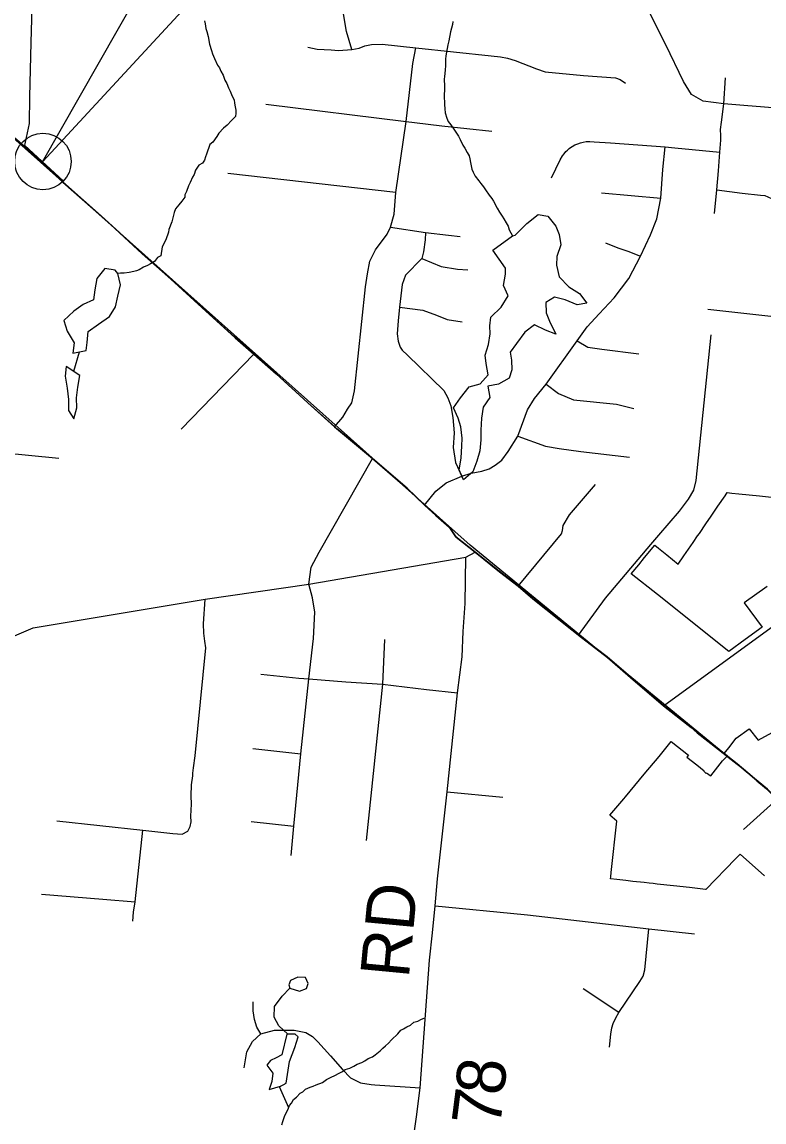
# Model space of a CAD drawing. Extents: x 0 to 39.3, y -3.9 to 22.
# Drawn here: x 2.954 to 3.818, y 18.6 to 19.881 of the extents above; entities that cross this region are included whole.
import ezdxf

# ---------------------------------------------------------------- set-up
doc = ezdxf.new("R2010")
doc.units = 0
for name, color, linetype in [('GM_X_City_Street', 7, 'Continuous'), ('GM_X_Corporation', 7, 'Continuous'), ('GM_X_County_Road', 7, 'Continuous'), ('GM_X_Minor_Lake', 7, 'Continuous'), ('GM_X_Minor_River', 7, 'Continuous'), ('GM_X_Rail_Line', 7, 'Continuous'), ('GM_X_State_Route', 7, 'Continuous'), ('GM_X_Township_Road', 7, 'Continuous'), ('GM_X_Township_Road_Text', 7, 'Continuous'), ('SH_Text', 7, 'Continuous')]:
    doc.layers.add(name, color=color, linetype=linetype)

msp = doc.modelspace()

# ---------------------------------------------------------------- linework, layer by layer
at = {"layer": 'GM_X_City_Street'}
msp.add_line((3.7939, 18.9401), (3.8332, 18.9754), dxfattribs=at)
at = {"layer": 'GM_X_Corporation'}
for points in [[(2.9304, 19.7584), (2.9564, 19.7359), (3.0012, 19.6948), (3.0459, 19.6551), (3.0936, 19.6114), (3.1268, 19.5818), (3.1629, 19.5487), (3.2017, 19.5136), (3.2232, 19.4946), (3.2494, 19.4715), (3.2862, 19.4376), (3.3175, 19.4096), (3.322, 19.4056), (3.3616, 19.3729), (3.4024, 19.3377), (3.4224, 19.3184), (3.4353, 19.3063), (3.4511, 19.2928), (3.4591, 19.2813), (3.4812, 19.2637), (3.5095, 19.241), (3.5312, 19.224), (3.5484, 19.2097), (3.6015, 19.1671), (3.6353, 19.1412), (3.6681, 19.1129), (3.7006, 19.0846), (3.7294, 19.0621), (3.7399, 19.0535), (3.7759, 19.0251), (3.7865, 19.0169), (3.7992, 19.0063), (3.8095, 18.9974), (3.8207, 18.988)], [(3.8207, 18.988), (3.8095, 18.9974), (3.7992, 19.0063), (3.7865, 19.0169), (3.7759, 19.0251), (3.7399, 19.0535), (3.7294, 19.0621), (3.7006, 19.0846), (3.6681, 19.1129), (3.6353, 19.1412), (3.6015, 19.1671), (3.5484, 19.2097), (3.5312, 19.224), (3.5095, 19.241), (3.4812, 19.2637), (3.4591, 19.2813), (3.4511, 19.2928), (3.4353, 19.3063), (3.4224, 19.3184), (3.4024, 19.3377), (3.3616, 19.3729), (3.322, 19.4056), (3.3175, 19.4096), (3.2862, 19.4376), (3.2494, 19.4715), (3.2232, 19.4946), (3.2017, 19.5136), (3.1629, 19.5487), (3.1268, 19.5818), (3.0936, 19.6114), (3.0459, 19.6551), (3.0012, 19.6948), (2.9564, 19.7359), (2.9304, 19.7584)], [(3.8216, 19.2234), (3.7948, 19.2043), (3.8157, 19.176), (3.7958, 19.1615), (3.7768, 19.1477), (3.6937, 19.2139), (3.6633, 19.2381), (3.672, 19.2487), (3.6788, 19.2572), (3.6906, 19.2716), (3.6951, 19.2679), (3.7047, 19.2602), (3.7181, 19.2494), (3.7247, 19.2591), (3.7301, 19.2669), (3.7352, 19.2745), (3.7405, 19.2822), (3.7426, 19.2852), (3.7502, 19.2964), (3.7562, 19.3051), (3.7643, 19.3169), (3.7726, 19.329), (3.7751, 19.3327), (3.7804, 19.3321), (3.7884, 19.3313), (3.8127, 19.3287), (3.8367, 19.3261)], [(3.8186, 18.8863), (3.7901, 18.9116), (3.7901, 18.9116), (3.7846, 18.9059), (3.75, 18.8704), (3.7499, 18.8703), (3.7342, 18.8721), (3.7312, 18.8725), (3.7123, 18.8746), (3.6935, 18.8767), (3.6889, 18.8772), (3.6843, 18.8777), (3.6785, 18.8783), (3.6653, 18.8798), (3.6568, 18.8807), (3.6466, 18.8819), (3.6391, 18.8827), (3.6394, 18.8849), (3.64, 18.8902), (3.64, 18.8902), (3.6466, 18.9501), (3.6385, 18.9568), (3.6546, 18.976), (3.6567, 18.9784), (3.6782, 19.0046), (3.6957, 19.0251), (3.7099, 19.0429), (3.7298, 19.0268), (3.7279, 19.0245), (3.7398, 19.0156), (3.7481, 19.0087), (3.7477, 19.0081), (3.7505, 19.0055), (3.7509, 19.0061), (3.7509, 19.0061), (3.7538, 19.0043), (3.7541, 19.004), (3.7558, 19.0029), (3.7696, 19.0202), (3.7749, 19.0258), (3.7749, 19.0258), (3.7751, 19.0261), (3.7716, 19.0289), (3.7768, 19.0354), (3.7855, 19.0465), (3.8005, 19.0575), (3.811, 19.0443), (3.8658, 19.0741)]]:
    msp.add_lwpolyline(points, dxfattribs=at)
at = {"layer": 'GM_X_County_Road'}
msp.add_line((3.7009, 19.0841), (3.8433, 19.1878), dxfattribs=at)
for points in [[(2.9644, 19.857), (2.9656, 19.8977), (2.9687, 19.9584)], [(2.9567, 19.7354), (2.9623, 19.7625), (2.9626, 19.7938), (2.9644, 19.857)], [(2.3872, 18.9634), (2.4076, 18.9796), (2.4185, 18.9873), (2.431, 18.9932), (2.4424, 18.9968), (2.4969, 19.0055), (2.5334, 19.0115), (2.6028, 19.0224), (2.6249, 19.0265), (2.6491, 19.0351), (2.6789, 19.0516), (2.7042, 19.0628), (2.7535, 19.0856), (2.8108, 19.1084), (2.9046, 19.1489), (2.9665, 19.175), (3.1671, 19.2085), (3.2876, 19.2261), (3.4707, 19.2576), (3.4814, 19.2631)]]:
    msp.add_lwpolyline(points, dxfattribs=at)
at = {"layer": 'GM_X_Minor_Lake'}
msp.add_line((3.0212, 19.4689), (3.0051, 19.4794), dxfattribs=at)
for points in [[(3.5249, 19.6318), (3.5282, 19.6327), (3.5417, 19.6461), (3.5548, 19.6565), (3.5662, 19.6548), (3.5755, 19.6432), (3.5795, 19.6333), (3.5812, 19.6211), (3.5764, 19.6075), (3.5763, 19.5976), (3.5795, 19.5839), (3.5907, 19.5723), (3.6031, 19.5645), (3.6116, 19.5533), (3.6002, 19.5512), (3.5862, 19.5572), (3.5737, 19.5604), (3.5637, 19.5541), (3.5643, 19.542), (3.5679, 19.5324), (3.5753, 19.5171), (3.5632, 19.5218), (3.5507, 19.5281), (3.5392, 19.5196), (3.5295, 19.5065), (3.5221, 19.4963), (3.5238, 19.4868), (3.524, 19.4758), (3.5212, 19.4659), (3.5085, 19.4589), (3.4963, 19.4565), (3.4984, 19.4435), (3.4909, 19.4322), (3.4888, 19.4194), (3.4882, 19.4053), (3.488, 19.3943), (3.487, 19.3814), (3.4834, 19.3693), (3.4786, 19.3568), (3.4678, 19.3475), (3.4627, 19.3586), (3.4652, 19.373), (3.4658, 19.3867), (3.4664, 19.3962), (3.4647, 19.4091), (3.4618, 19.4194), (3.4563, 19.4313), (3.4645, 19.443), (3.4746, 19.4557), (3.4872, 19.4593), (3.4965, 19.4698), (3.4941, 19.4831), (3.4931, 19.4926), (3.4971, 19.5051), (3.4989, 19.5176), (3.4986, 19.5271), (3.4996, 19.537), (3.5119, 19.5486), (3.5198, 19.5617), (3.5143, 19.574), (3.5168, 19.5872)], [(3.5168, 19.5872), (3.5169, 19.5941), (3.502, 19.6152), (3.5249, 19.6318)], [(3.0651, 19.5879), (3.0621, 19.5917), (3.05, 19.5938), (3.041, 19.5822), (3.0385, 19.5689), (3.0368, 19.5572), (3.0249, 19.5517), (3.0141, 19.5439), (3.0025, 19.5331), (3.0061, 19.5208), (3.0143, 19.507), (3.0129, 19.4949)], [(3.0282, 19.498), (3.0295, 19.5075), (3.0308, 19.5204), (3.0428, 19.5289), (3.0555, 19.5378), (3.0625, 19.5491), (3.0654, 19.5616), (3.0683, 19.5745), (3.0651, 19.5879)], [(3.0051, 19.4794), (3.0041, 19.4684), (3.0061, 19.4543), (3.0078, 19.441), (3.008, 19.4284), (3.0139, 19.4185), (3.0175, 19.4313), (3.017, 19.4431), (3.0187, 19.4556), (3.0212, 19.4689)], [(3.2838, 18.7679), (3.275, 18.7681), (3.2662, 18.7644), (3.2646, 18.7592), (3.2657, 18.7553)], [(3.2657, 18.7553), (3.2767, 18.7521), (3.2851, 18.755), (3.2871, 18.761), (3.2838, 18.7679)], [(3.2535, 18.6404), (3.2612, 18.6448), (3.2654, 18.6698), (3.2714, 18.6864), (3.2754, 18.6989), (3.272, 18.702), (3.2621, 18.7018), (3.2564, 18.6776), (3.2495, 18.6743), (3.243, 18.671), (3.2387, 18.6657)]]:
    msp.add_lwpolyline(points, dxfattribs=at)
at = {"layer": 'GM_X_Minor_River'}
for p, q in [((3.0129, 19.4949), (3.0282, 19.498)), ((3.0201, 19.4963), (3.0136, 19.4739))]:
    msp.add_line(p, q, dxfattribs=at)
for points in [[(3.1664, 19.8822), (3.1671, 19.8788), (3.1678, 19.8731), (3.1689, 19.8697), (3.1703, 19.8639), (3.1721, 19.8552), (3.1742, 19.8475), (3.1757, 19.8437), (3.1779, 19.8383), (3.1815, 19.8307), (3.1838, 19.8276), (3.1852, 19.8234), (3.1878, 19.8188), (3.19, 19.813), (3.1922, 19.8092), (3.194, 19.8042), (3.1962, 19.8004), (3.1984, 19.7946), (3.2006, 19.79), (3.2013, 19.7862), (3.202, 19.782), (3.2027, 19.7782), (3.2026, 19.7748), (3.2022, 19.7706), (3.1976, 19.7661), (3.1925, 19.7605), (3.1883, 19.7571), (3.1829, 19.7515), (3.1805, 19.7474), (3.1759, 19.741), (3.1724, 19.738), (3.1712, 19.7346), (3.1696, 19.7305), (3.1684, 19.7267), (3.1672, 19.7237), (3.1664, 19.7199), (3.164, 19.7165), (3.1598, 19.7139), (3.1559, 19.7083), (3.1543, 19.703), (3.1524, 19.7)], [(3.4554, 19.8814), (3.4549, 19.8779), (3.4529, 19.8692), (3.4508, 19.859), (3.4496, 19.8541), (3.4487, 19.8499), (3.4475, 19.8416), (3.447, 19.8374), (3.4469, 19.8302), (3.4464, 19.8249), (3.4459, 19.8173), (3.4455, 19.8142), (3.4457, 19.8062), (3.4455, 19.7918), (3.4458, 19.7887), (3.4458, 19.7846), (3.446, 19.7796), (3.4464, 19.7751), (3.4485, 19.7689), (3.45, 19.7651), (3.453, 19.7609), (3.4574, 19.7547), (3.4619, 19.7478), (3.4641, 19.7439), (3.467, 19.7374), (3.4696, 19.734), (3.4722, 19.729), (3.4744, 19.7251), (3.4751, 19.7213), (3.4762, 19.7171), (3.4776, 19.7095), (3.479, 19.706), (3.4816, 19.7014), (3.4857, 19.696), (3.4879, 19.6926), (3.4913, 19.6887), (3.4935, 19.6852), (3.4976, 19.6791), (3.5009, 19.6752), (3.5028, 19.6722), (3.5072, 19.6641), (3.5098, 19.6595), (3.5131, 19.6545), (3.515, 19.6514), (3.5176, 19.6468), (3.5198, 19.643), (3.5209, 19.6387), (3.5249, 19.6318)], [(3.1524, 19.7), (3.1496, 19.6939), (3.1476, 19.6898), (3.1452, 19.6834), (3.1433, 19.6796), (3.1432, 19.6766), (3.1397, 19.6721), (3.1362, 19.6679), (3.1323, 19.6631), (3.1307, 19.6589), (3.1283, 19.6479), (3.1247, 19.6392), (3.1243, 19.6362), (3.1211, 19.6271), (3.1171, 19.6188), (3.1155, 19.6086), (3.1116, 19.6064), (3.1081, 19.6019), (3.1035, 19.5993), (3.0997, 19.5971), (3.0951, 19.5953), (3.0901, 19.5923), (3.087, 19.5908), (3.084, 19.5901), (3.0786, 19.5891), (3.0725, 19.5884), (3.0684, 19.5881), (3.0645, 19.5878)], [(3.2633, 18.7018), (3.2528, 18.7115), (3.2473, 18.7218), (3.2479, 18.734), (3.2568, 18.746), (3.2657, 18.7553)], [(3.398, 18.7079), (3.4018, 18.7105), (3.406, 18.7123), (3.4099, 18.7157), (3.4145, 18.7171), (3.4191, 18.7193), (3.4221, 18.7204)], [(3.2562, 18.5963), (3.2574, 18.6001), (3.2598, 18.6069), (3.2633, 18.6136), (3.2653, 18.6186), (3.2676, 18.6216), (3.27, 18.6257), (3.2735, 18.6283), (3.2777, 18.6332), (3.2808, 18.6346), (3.2839, 18.6376), (3.2892, 18.6402), (3.2927, 18.6413), (3.2961, 18.6427), (3.3038, 18.6456), (3.3084, 18.649), (3.3138, 18.6519), (3.318, 18.6538), (3.323, 18.6563), (3.3268, 18.6582), (3.3299, 18.6608), (3.3356, 18.6622), (3.3402, 18.6644), (3.3441, 18.667), (3.3494, 18.6688), (3.3529, 18.6707), (3.3567, 18.6736), (3.3617, 18.6754), (3.3651, 18.6777), (3.3709, 18.6825), (3.374, 18.6855), (3.3771, 18.6881), (3.3806, 18.6915), (3.3841, 18.6952), (3.3914, 18.7023), (3.3949, 18.7064), (3.398, 18.7079)], [(3.2387, 18.6657), (3.2458, 18.6565), (3.2445, 18.6466), (3.2416, 18.6375), (3.2549, 18.6412)], [(3.2643, 18.616), (3.2535, 18.6404)]]:
    msp.add_lwpolyline(points, dxfattribs=at)
at = {"layer": 'GM_X_Rail_Line'}
msp.add_lwpolyline([(4.1862, 18.6283), (3.8218, 18.9873), (3.4757, 19.2713), (2.7497, 19.9187), (2.5534, 20.0926), (2.2306, 20.3947), (2.1828, 20.4326), (2.1273, 20.4658), (1.9, 20.5708)], dxfattribs=at)
at = {"layer": 'GM_X_State_Route'}
for points in [[(2.4407, 20.1946), (2.467, 20.1691), (2.4839, 20.1538), (2.5192, 20.122), (2.5514, 20.0919), (2.5881, 20.0598), (2.6266, 20.0259), (2.6555, 20.0001), (2.6898, 19.9706), (2.7204, 19.944), (2.7517, 19.9166), (2.8058, 19.8682), (2.8175, 19.858), (2.8464, 19.8327), (2.8874, 19.7968), (2.8948, 19.7902), (2.9306, 19.7578), (2.9567, 19.7354)], [(2.9567, 19.7354), (3.0014, 19.6943), (3.0462, 19.6545), (3.0938, 19.6109), (3.127, 19.5813), (3.1631, 19.5481), (3.2019, 19.5131), (3.2235, 19.494), (3.2496, 19.471), (3.2865, 19.4371), (3.3178, 19.4091), (3.3619, 19.3723), (3.4026, 19.3372), (3.4226, 19.3179), (3.4355, 19.3058), (3.4513, 19.2923), (3.4594, 19.2807), (3.4814, 19.2631), (3.5098, 19.2405), (3.5314, 19.2235), (3.5486, 19.2091), (3.5939, 19.1729)], [(3.5939, 19.1729), (3.6018, 19.1666), (3.6355, 19.1407), (3.6684, 19.1123), (3.7009, 19.0841), (3.7296, 19.0616), (3.7329, 19.0589)], [(3.7329, 19.0589), (3.7401, 19.053), (3.7737, 19.0266)], [(3.7737, 19.0266), (3.7761, 19.0246), (3.7867, 19.0163), (3.7897, 19.0139)], [(3.7897, 19.0139), (3.7994, 19.0058), (3.8097, 18.9969), (3.8209, 18.9875), (3.8332, 18.9754), (3.8416, 18.9671), (3.8461, 18.9624), (3.8553, 18.9541), (3.8757, 18.9339)]]:
    msp.add_lwpolyline(points, dxfattribs=at)
at = {"layer": 'GM_X_Township_Road'}
for p, q in [((3.3891, 19.6821), (3.1934, 19.7044)), ((3.6285, 19.6818), (3.6976, 19.6755)), ((3.4505, 19.6324), (3.4639, 19.6308)), ((4.0089, 19.5177), (3.7525, 19.5459)), ((3.1391, 19.4065), (3.2235, 19.494)), ((2.9296, 19.3794), (2.9967, 19.3727)), ((3.2227, 19.0345), (3.2783, 19.0283)), ((3.4487, 18.9841), (3.5137, 18.9779)), ((3.2207, 18.9495), (3.2704, 18.9441)), ((3.6489, 18.7272), (3.6071, 18.7545)), ((3.3647, 18.6427), (3.4174, 18.6393))]:
    msp.add_line(p, q, dxfattribs=at)
for points in [[(3.338, 19.8487), (3.3316, 19.8697), (3.3283, 19.8903), (3.3274, 19.9042), (3.3285, 19.9146), (3.3314, 19.9292), (3.3408, 19.9553), (3.3533, 19.9796), (3.3613, 19.9984), (3.3703, 20.0145), (3.3743, 20.0291), (3.3761, 20.0347)], [(4.0319, 19.7865), (4.0104, 19.7862), (3.997, 19.7878), (3.9771, 19.7901), (3.95, 19.7927), (3.9187, 19.7953), (3.9008, 19.7966), (3.8806, 19.7934), (3.8645, 19.7854), (3.8473, 19.7813), (3.832, 19.7803), (3.8186, 19.7816), (3.7945, 19.7836), (3.7711, 19.7857), (3.7472, 19.7888), (3.7335, 19.7963), (3.7243, 19.8116), (3.7035, 19.8543), (3.6849, 19.891)], [(3.2865, 19.8514), (3.2974, 19.8491), (3.3137, 19.8485), (3.3221, 19.8476), (3.338, 19.8487), (3.3464, 19.8503), (3.3531, 19.8531), (3.3608, 19.8547), (3.373, 19.8549), (3.4125, 19.8507), (3.5002, 19.8414), (3.511, 19.8401), (3.519, 19.8387), (3.5282, 19.836), (3.553, 19.8262), (3.563, 19.8226), (3.6077, 19.8187), (3.6449, 19.8156), (3.6504, 19.8137), (3.6567, 19.8095)], [(3.3827, 19.6418), (3.3872, 19.6571), (3.3891, 19.6821), (3.401, 19.7648), (3.409, 19.8323), (3.4125, 19.8507)], [(3.7601, 19.6576), (3.7631, 19.6852), (3.7648, 19.7074), (3.7664, 19.7292), (3.7677, 19.743), (3.7678, 19.7486), (3.7674, 19.7556), (3.7684, 19.7641), (3.7711, 19.7857), (3.7731, 19.8159)], [(3.2376, 19.7852), (3.401, 19.7648), (3.4109, 19.7637)], [(3.4109, 19.7637), (3.4428, 19.76), (3.5008, 19.7536)], [(3.4661, 19.3517), (3.4768, 19.3552), (3.4892, 19.3575), (3.4976, 19.3604), (3.5049, 19.3646), (3.5127, 19.3705), (3.52, 19.3807), (3.5312, 19.3982), (3.5425, 19.4291), (3.5506, 19.4421), (3.5643, 19.459), (3.6001, 19.5094), (3.6119, 19.5256), (3.626, 19.5408), (3.6433, 19.5596), (3.6603, 19.5819), (3.674, 19.608), (3.6857, 19.6328), (3.6932, 19.6517), (3.6976, 19.6755), (3.6999, 19.7089), (3.7029, 19.7354)], [(3.5704, 19.6994), (3.5806, 19.7204), (3.5831, 19.7249), (3.585, 19.7274), (3.5871, 19.7299), (3.5889, 19.7316), (3.5909, 19.7333), (3.5924, 19.7345), (3.5946, 19.736), (3.5975, 19.7376), (3.6009, 19.7391), (3.6043, 19.7402), (3.6073, 19.7409), (3.6106, 19.7415), (3.6132, 19.7416), (3.6152, 19.7416), (3.62, 19.7414), (3.639, 19.7401), (3.7029, 19.7354), (3.7142, 19.7343), (3.7664, 19.7292)], [(3.7631, 19.6852), (3.7925, 19.6815), (3.8137, 19.6793), (3.8187, 19.6786), (3.8224, 19.677), (3.8274, 19.6749), (3.8306, 19.6734), (3.8347, 19.6713), (3.8398, 19.6674), (3.843, 19.6639), (3.8484, 19.6588), (3.8539, 19.6516), (3.8692, 19.6327), (3.8759, 19.6265), (3.9041, 19.5944)], [(3.3178, 19.4091), (3.3273, 19.4204), (3.3326, 19.4299), (3.3379, 19.4372), (3.3409, 19.4511), (3.3539, 19.5722), (3.3562, 19.5874), (3.3586, 19.6023), (3.3654, 19.6155), (3.379, 19.6338), (3.3827, 19.6418), (3.4238, 19.6357), (3.4505, 19.6324)], [(3.4238, 19.6357), (3.4234, 19.627), (3.4213, 19.6132), (3.4193, 19.6053), (3.4004, 19.5858), (3.3966, 19.5752), (3.3932, 19.5485), (3.3919, 19.5329), (3.3905, 19.5177), (3.3916, 19.509), (3.3943, 19.5019), (3.3963, 19.4985), (3.4025, 19.4928), (3.4448, 19.4515), (3.4496, 19.4429), (3.453, 19.4336), (3.4556, 19.4202), (3.4569, 19.4023), (3.456, 19.385), (3.4587, 19.3677), (3.4661, 19.3517)], [(3.6332, 19.6236), (3.6477, 19.6179), (3.6594, 19.6137), (3.674, 19.608)], [(3.4193, 19.6053), (3.4418, 19.5962), (3.4609, 19.5931), (3.4728, 19.5921)], [(3.3932, 19.5485), (3.4205, 19.5453), (3.4365, 19.5393), (3.4488, 19.5343), (3.4664, 19.5314)], [(3.6954, 19.2829), (3.7196, 19.311), (3.7298, 19.3252), (3.7361, 19.3356), (3.7387, 19.3466), (3.7564, 19.5163)], [(3.6001, 19.5094), (3.6127, 19.5019), (3.6291, 19.4996), (3.6722, 19.4944)], [(3.5643, 19.459), (3.5787, 19.4481), (3.5959, 19.4407), (3.6459, 19.4358), (3.6663, 19.4306)], [(3.5312, 19.3982), (3.5634, 19.3869), (3.5792, 19.3842), (3.6045, 19.3806), (3.6614, 19.374)], [(3.2876, 19.2261), (3.2904, 19.2457), (3.2997, 19.2632), (3.3619, 19.3723)], [(3.4226, 19.3179), (3.4357, 19.3342), (3.4476, 19.3439), (3.4661, 19.3517)], [(3.5314, 19.2235), (3.5821, 19.2845), (3.5831, 19.2884), (3.5839, 19.2943), (3.5915, 19.3066), (3.6215, 19.342)], [(3.6018, 19.1666), (3.6332, 19.2095), (3.6862, 19.2723), (3.6954, 19.2829)], [(3.2948, 18.4149), (3.3024, 18.4287), (3.3787, 18.5282), (3.4008, 18.5583), (3.4083, 18.5733), (3.4099, 18.5836), (3.4131, 18.6057), (3.4174, 18.6393), (3.4281, 18.7882), (3.4317, 18.8199), (3.435, 18.8512), (3.4375, 18.8828), (3.4487, 18.9841), (3.461, 19.0993), (3.4665, 19.1413), (3.4676, 19.1707), (3.47, 19.2036), (3.4707, 19.2576)], [(3.2673, 18.9101), (3.2704, 18.9441), (3.2783, 19.0283), (3.2878, 19.1159), (3.2931, 19.1627), (3.2946, 19.1932), (3.292, 19.2099), (3.2876, 19.2261)], [(3.1528, 19.0059), (3.1535, 19.0121), (3.1552, 19.0261), (3.1678, 19.1517), (3.1666, 19.1595), (3.1654, 19.1688), (3.165, 19.1796), (3.1671, 19.2085)], [(3.3758, 19.1617), (3.3734, 19.1094), (3.3546, 18.9274)], [(3.2318, 19.1213), (3.2762, 19.1164), (3.2878, 19.1159), (3.331, 19.1122), (3.3734, 19.1094), (3.4248, 19.1033), (3.461, 19.0993)], [(2.9943, 18.9502), (3.0945, 18.9393), (3.1293, 18.9355), (3.1403, 18.9346), (3.1468, 18.9381), (3.1495, 18.9437), (3.1508, 18.9493), (3.1504, 18.9558), (3.1509, 18.9696), (3.1507, 18.9795), (3.1512, 18.9924), (3.1525, 19.0028), (3.1528, 19.0059)], [(3.0828, 18.8335), (3.0837, 18.8441), (3.0855, 18.8559), (3.0945, 18.9393)], [(2.9762, 18.865), (3.0477, 18.8589), (3.0855, 18.8559)], [(3.435, 18.8512), (3.5386, 18.8414), (3.5425, 18.841)], [(3.5425, 18.841), (3.6837, 18.8245), (3.7371, 18.8186)], [(3.6381, 18.6866), (3.6395, 18.7019), (3.6407, 18.7093), (3.6423, 18.7144), (3.6455, 18.7208), (3.6489, 18.7272), (3.6734, 18.7632), (3.677, 18.7692), (3.679, 18.7769), (3.6837, 18.8245)], [(3.232, 18.7024), (3.2271, 18.7099), (3.2244, 18.7188), (3.2228, 18.7289), (3.2228, 18.7395)], [(3.2126, 18.6626), (3.2155, 18.6813), (3.2222, 18.6931), (3.232, 18.7024), (3.2477, 18.7063), (3.2707, 18.7065), (3.2841, 18.7036), (3.2919, 18.6992), (3.2984, 18.6929), (3.313, 18.6764), (3.3269, 18.6605), (3.3364, 18.6508), (3.348, 18.6452), (3.3605, 18.643), (3.3647, 18.6427)]]:
    msp.add_lwpolyline(points, dxfattribs=at)
at = {"layer": 'SH_Text'}
for p, q in [((2.9777, 19.7179), (3.5607, 20.744)), ((2.9781, 19.7184), (3.5607, 20.3507)), ((2.9568, 19.7368), (3.0016, 19.6957))]:
    msp.add_line(p, q, dxfattribs=at)
msp.add_circle((2.9781, 19.7184), 0.0329, dxfattribs=at)

# ---------------------------------------------------------------- texts
at = {"layer": 'GM_X_Township_Road_Text'}
for s, height, rotation, p in [('RD', 0.05682, 84.5897, (3.4041, 18.766)), ('8', 0.0568, 84.8493, (3.5149, 18.6294)), ('7', 0.0568, 82.718, (3.5102, 18.5924))]:
    msp.add_text(s, height=height, rotation=rotation, dxfattribs=at).set_placement(p)

doc.saveas('drawing.dxf')
